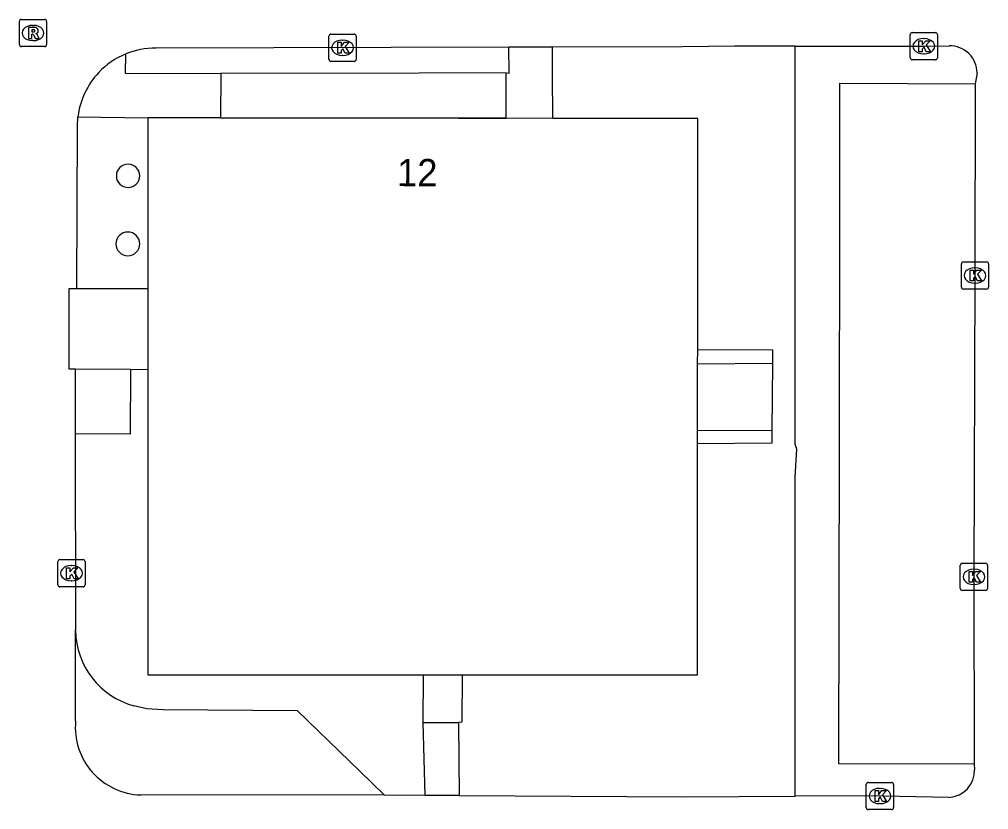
# Model space of a CAD drawing. Extents: x 161477 to 163040, y 383680 to 384868.
# Drawn here: x 161893.36 to 161928.97, y 384085.24 to 384114.29 of the extents above; entities that cross this region are included whole.
import ezdxf

# ---------------------------------------------------------------- set-up
doc = ezdxf.new("R2010")
doc.units = 0
for name, color, linetype in [('IMGEO_Dek', 7, 'Continuous'), ('IMGEO_Kolk', 7, 'Continuous'), ('IMGEO_Opslagtank', 7, 'Continuous'), ('IMGEO_Pand', 7, 'Continuous'), ('IMGEO_Pand_nummerreeks', 7, 'Continuous'), ('IMGEO_Parkeervlak_open', 7, 'Continuous'), ('IMGEO_Rijbaan_lokaal_open', 7, 'Continuous'), ('IMGEO_Rioolput', 7, 'Continuous'), ('IMGEO_Voetpad_halfverhard', 7, 'Continuous'), ('IMGEO_Voetpad_open', 7, 'Continuous')]:
    doc.layers.add(name, color=color, linetype=linetype)

msp = doc.modelspace()

# ---------------------------------------------------------------- linework, layer by layer
at = {"layer": 'IMGEO_Dek'}
msp.add_lwpolyline([(161911.242, 384112.317), (161908.043, 384112.311), (161900.763, 384112.296), (161900.748, 384110.668), (161909.493, 384110.653), (161911.237, 384110.65)], close=True, dxfattribs=at)
at = {"layer": 'IMGEO_Kolk'}
for p, q in [((161904.731, 384112.818), (161904.731, 384113.67)), ((161904.806, 384113.744), (161905.658, 384113.744)), ((161905.732, 384113.67), (161905.732, 384112.818)), ((161926.086, 384112.873), (161926.086, 384113.725)), ((161926.161, 384113.799), (161927.013, 384113.799)), ((161927.087, 384113.725), (161927.087, 384112.873)), ((161905.219, 384113.524), (161905.244, 384113.524)), ((161926.574, 384113.579), (161926.599, 384113.579)), ((161905.242, 384112.964), (161905.217, 384112.964)), ((161926.597, 384113.019), (161926.572, 384113.019)), ((161905.658, 384112.744), (161904.806, 384112.744)), ((161927.013, 384112.799), (161926.161, 384112.799)), ((161927.966, 384104.446), (161927.966, 384105.298)), ((161928.041, 384105.372), (161928.893, 384105.372)), ((161928.454, 384105.152), (161928.479, 384105.152)), ((161928.967, 384105.298), (161928.967, 384104.446)), ((161928.477, 384104.592), (161928.452, 384104.592)), ((161928.893, 384104.372), (161928.041, 384104.372)), ((161894.773, 384093.502), (161894.773, 384094.354)), ((161894.848, 384094.428), (161895.7, 384094.428)), ((161895.261, 384094.208), (161895.286, 384094.208)), ((161895.774, 384094.354), (161895.774, 384093.502)), ((161927.928, 384093.37), (161927.928, 384094.222)), ((161928.003, 384094.296), (161928.855, 384094.296)), ((161928.929, 384094.222), (161928.929, 384093.37)), ((161928.416, 384094.076), (161928.441, 384094.076)), ((161895.7, 384093.428), (161894.848, 384093.428)), ((161895.284, 384093.648), (161895.259, 384093.648)), ((161928.439, 384093.516), (161928.414, 384093.516)), ((161928.855, 384093.296), (161928.003, 384093.296)), ((161924.474, 384085.313), (161924.474, 384086.165)), ((161924.549, 384086.239), (161925.401, 384086.239)), ((161924.962, 384086.019), (161924.987, 384086.019)), ((161925.475, 384086.165), (161925.475, 384085.313)), ((161925.401, 384085.239), (161924.549, 384085.239)), ((161924.985, 384085.459), (161924.96, 384085.459))]:
    msp.add_line(p, q, dxfattribs=at)
for points in [[(161904.731, 384112.818), (161904.731, 384113.67)], [(161904.806, 384113.744), (161905.658, 384113.744)], [(161905.732, 384113.67), (161905.732, 384112.818)], [(161926.086, 384112.873), (161926.086, 384113.725)], [(161926.161, 384113.799), (161927.013, 384113.799)], [(161927.087, 384113.725), (161927.087, 384112.873)], [(161905.052, 384113.444), (161905.175, 384113.444), (161905.175, 384113.293), (161905.305, 384113.444), (161905.469, 384113.444), (161905.323, 384113.293), (161905.476, 384113.044), (161905.324, 384113.044), (161905.239, 384113.208), (161905.175, 384113.141), (161905.175, 384113.044), (161905.052, 384113.044), (161905.052, 384113.444)], [(161926.407, 384113.499), (161926.53, 384113.499), (161926.53, 384113.348), (161926.66, 384113.499), (161926.824, 384113.499), (161926.678, 384113.348), (161926.831, 384113.099), (161926.679, 384113.099), (161926.594, 384113.263), (161926.53, 384113.196), (161926.53, 384113.099), (161926.407, 384113.099), (161926.407, 384113.499)], [(161905.658, 384112.744), (161904.806, 384112.744)], [(161927.013, 384112.799), (161926.161, 384112.799)], [(161927.966, 384104.446), (161927.966, 384105.298)], [(161928.041, 384105.372), (161928.893, 384105.372)], [(161928.967, 384105.298), (161928.967, 384104.446)], [(161928.287, 384105.072), (161928.41, 384105.072), (161928.41, 384104.921), (161928.54, 384105.072), (161928.704, 384105.072), (161928.558, 384104.921), (161928.711, 384104.672), (161928.559, 384104.672), (161928.474, 384104.836), (161928.41, 384104.769), (161928.41, 384104.672), (161928.287, 384104.672), (161928.287, 384105.072)], [(161928.893, 384104.372), (161928.041, 384104.372)], [(161894.773, 384093.502), (161894.773, 384094.354)], [(161894.848, 384094.428), (161895.7, 384094.428)], [(161895.094, 384094.128), (161895.217, 384094.128), (161895.217, 384093.977), (161895.347, 384094.128), (161895.511, 384094.128), (161895.365, 384093.977), (161895.518, 384093.728), (161895.366, 384093.728), (161895.281, 384093.892), (161895.217, 384093.825), (161895.217, 384093.728), (161895.094, 384093.728), (161895.094, 384094.128)], [(161895.774, 384094.354), (161895.774, 384093.502)], [(161927.928, 384093.37), (161927.928, 384094.222)], [(161928.003, 384094.296), (161928.855, 384094.296)], [(161928.929, 384094.222), (161928.929, 384093.37)], [(161928.249, 384093.996), (161928.372, 384093.996), (161928.372, 384093.845), (161928.502, 384093.996), (161928.666, 384093.996), (161928.52, 384093.845), (161928.673, 384093.596), (161928.521, 384093.596), (161928.436, 384093.76), (161928.372, 384093.693), (161928.372, 384093.596), (161928.249, 384093.596), (161928.249, 384093.996)], [(161895.7, 384093.428), (161894.848, 384093.428)], [(161928.855, 384093.296), (161928.003, 384093.296)], [(161924.474, 384085.313), (161924.474, 384086.165)], [(161924.549, 384086.239), (161925.401, 384086.239)], [(161924.795, 384085.939), (161924.918, 384085.939), (161924.918, 384085.788), (161925.048, 384085.939), (161925.212, 384085.939), (161925.066, 384085.788), (161925.219, 384085.539), (161925.067, 384085.539), (161924.982, 384085.703), (161924.918, 384085.636), (161924.918, 384085.539), (161924.795, 384085.539), (161924.795, 384085.939)], [(161925.475, 384086.165), (161925.475, 384085.313)], [(161925.401, 384085.239), (161924.549, 384085.239)]]:
    msp.add_lwpolyline(points, dxfattribs=at)
for centre, start, end in [((161904.808, 384113.668), 91.552, 178.448), ((161904.808, 384113.668), 91.552, 178.448), ((161905.656, 384113.668), 1.552, 88.448), ((161905.656, 384113.668), 1.552, 88.448), ((161926.163, 384113.723), 91.552, 178.448), ((161926.163, 384113.723), 91.552, 178.448), ((161927.011, 384113.723), 1.552, 88.448), ((161927.011, 384113.723), 1.552, 88.448), ((161904.808, 384112.82), 181.552, 268.448), ((161904.808, 384112.82), 181.552, 268.448), ((161905.656, 384112.82), 271.552, 358.448), ((161905.656, 384112.82), 271.552, 358.448), ((161926.163, 384112.875), 181.552, 268.448), ((161926.163, 384112.875), 181.552, 268.448), ((161927.011, 384112.875), 271.552, 358.448), ((161927.011, 384112.875), 271.552, 358.448), ((161928.043, 384105.296), 91.552, 178.448), ((161928.043, 384105.296), 91.552, 178.448), ((161928.891, 384105.296), 1.552, 88.448), ((161928.891, 384105.296), 1.552, 88.448), ((161928.043, 384104.448), 181.552, 268.448), ((161928.043, 384104.448), 181.552, 268.448), ((161928.891, 384104.448), 271.552, 358.448), ((161928.891, 384104.448), 271.552, 358.448), ((161894.85, 384094.352), 91.552, 178.448), ((161894.85, 384094.352), 91.552, 178.448), ((161895.698, 384094.352), 1.552, 88.448), ((161895.698, 384094.352), 1.552, 88.448), ((161928.005, 384094.22), 91.552, 178.448), ((161928.005, 384094.22), 91.552, 178.448), ((161928.853, 384094.22), 1.552, 88.448), ((161928.853, 384094.22), 1.552, 88.448), ((161894.85, 384093.504), 181.552, 268.448), ((161894.85, 384093.504), 181.552, 268.448), ((161895.698, 384093.504), 271.552, 358.448), ((161895.698, 384093.504), 271.552, 358.448), ((161928.005, 384093.372), 181.552, 268.448), ((161928.005, 384093.372), 181.552, 268.448), ((161928.853, 384093.372), 271.552, 358.448), ((161928.853, 384093.372), 271.552, 358.448), ((161924.551, 384086.163), 91.552, 178.448), ((161924.551, 384086.163), 91.552, 178.448), ((161925.399, 384086.163), 1.552, 88.448), ((161925.399, 384086.163), 1.552, 88.448), ((161924.551, 384085.315), 181.552, 268.448), ((161924.551, 384085.315), 181.552, 268.448), ((161925.399, 384085.315), 271.552, 358.448), ((161925.399, 384085.315), 271.552, 358.448)]:
    msp.add_arc(centre, 0.0765, start, end, dxfattribs=at)
for centre, major_axis, ratio, start_param, end_param in [((161905.218, 384113.244), (-0.387, 0.002), 0.722429, 4.712389, 7.853982), ((161905.243, 384113.244), (-0.39, 0.002), 0.717154, 1.570796, 4.712389), ((161926.573, 384113.299), (-0.387, 0.002), 0.722429, 4.712389, 7.853982), ((161926.598, 384113.299), (-0.39, 0.002), 0.717154, 1.570796, 4.712389), ((161928.453, 384104.872), (-0.387, 0.002), 0.722429, 4.712389, 7.853982), ((161928.478, 384104.872), (-0.39, 0.002), 0.717154, 1.570796, 4.712389), ((161895.26, 384093.928), (-0.387, 0.002), 0.722429, 4.712389, 7.853982), ((161895.285, 384093.928), (-0.39, 0.002), 0.717154, 1.570796, 4.712389), ((161928.415, 384093.796), (-0.387, 0.002), 0.722429, 4.712389, 7.853982), ((161928.44, 384093.796), (-0.39, 0.002), 0.717154, 1.570796, 4.712389), ((161924.961, 384085.739), (-0.387, 0.002), 0.722429, 4.712389, 7.853982), ((161924.986, 384085.739), (-0.39, 0.002), 0.717154, 1.570796, 4.712389)]:
    msp.add_ellipse(centre, major_axis=major_axis, ratio=ratio, start_param=start_param, end_param=end_param, dxfattribs=at)
at = {"layer": 'IMGEO_Opslagtank'}
for centre, radius, start, end in [((161897.351, 384108.535), 0.428, 359.933, 269.933), ((161897.35, 384108.536), 0.428, 270.0648, 359.8012), ((161897.342, 384106.033), 0.437, 90.0656, 359.9344), ((161897.341, 384106.032), 0.437, 0.0025, 89.9975)]:
    msp.add_arc(centre, radius, start, end, dxfattribs=at)
at = {"layer": 'IMGEO_Pand'}
for points in [[(161898.081, 384110.673), (161898.08, 384104.395)], [(161900.748, 384110.668), (161898.081, 384110.673)], [(161911.237, 384110.65), (161909.493, 384110.653), (161900.748, 384110.668)], [(161912.952, 384110.647), (161911.237, 384110.65)], [(161918.279, 384102.154), (161918.288, 384110.637), (161912.952, 384110.647)], [(161898.08, 384104.395), (161898.079, 384101.41)], [(161918.278, 384101.63), (161918.279, 384102.154)], [(161918.276, 384099.17), (161918.278, 384101.63)], [(161898.079, 384101.41), (161898.078, 384096.699), (161898.078, 384094.245), (161898.077, 384090.199), (161908.204, 384090.196)], [(161918.275, 384098.69), (161918.276, 384099.17)], [(161909.624, 384090.196), (161918.266, 384090.194), (161918.275, 384098.69)], [(161908.204, 384090.196), (161909.624, 384090.196)]]:
    msp.add_lwpolyline(points, dxfattribs=at)
at = {"layer": 'IMGEO_Parkeervlak_open'}
msp.add_lwpolyline([(161928.44, 384086.908), (161923.462, 384086.921), (161923.483, 384098.676), (161923.503, 384107.023), (161923.498, 384111.939), (161928.47, 384111.914)], dxfattribs=at)
at = {"layer": 'IMGEO_Rijbaan_lokaal_open'}
for points in [[(161911.338, 384113.266), (161898.379, 384113.23)], [(161912.946, 384113.27), (161911.338, 384113.266)], [(161921.866, 384113.297), (161919.637, 384113.296), (161917.724, 384113.283), (161912.946, 384113.27)], [(161921.866, 384113.297), (161926.587, 384113.3), (161927.523, 384113.312)], [(161928.542, 384112.318), (161928.47, 384111.914)], [(161928.47, 384111.914), (161928.467, 384104.873), (161928.429, 384093.797), (161928.44, 384086.908)], [(161895.469, 384104.397), (161895.491, 384110.351), (161895.511, 384110.71)], [(161895.422, 384101.427), (161895.192, 384101.427), (161895.189, 384104.397), (161895.469, 384104.397)], [(161895.424, 384099.051), (161895.422, 384101.427)], [(161895.426, 384091.816), (161895.427, 384091.877), (161895.429, 384094.247), (161895.426, 384096.705), (161895.424, 384099.051)], [(161895.423, 384088.499), (161895.426, 384091.816)], [(161928.44, 384086.908), (161928.451, 384086.709)], [(161906.777, 384085.765), (161897.819, 384085.777)], [(161908.266, 384085.762), (161906.777, 384085.765)], [(161909.516, 384085.763), (161908.266, 384085.762)], [(161909.516, 384085.763), (161917.738, 384085.714), (161921.866, 384085.737)], [(161927.512, 384085.687), (161924.475, 384085.751), (161921.866, 384085.737)]]:
    msp.add_lwpolyline(points, dxfattribs=at)
for centre, radius, start, end in [((161898.349, 384110.382), 2.849, 112.6072, 136.7222), ((161898.35, 384110.369), 2.861, 89.4148, 112.5186), ((161927.55, 384112.32), 0.992, 359.8798, 91.5432), ((161898.348, 384110.368), 2.857, 136.506, 173.1325), ((161897.905, 384088.268), 2.493, 174.6836, 268.0271), ((161927.46, 384086.677), 0.991, 272.9889, 1.8583)]:
    msp.add_arc(centre, radius, start, end, dxfattribs=at)
at = {"layer": 'IMGEO_Rioolput'}
for p, q in [((161893.358, 384113.36), (161893.358, 384114.212)), ((161893.433, 384114.286), (161894.285, 384114.286)), ((161893.846, 384114.066), (161893.871, 384114.066)), ((161894.359, 384114.212), (161894.359, 384113.36)), ((161893.869, 384113.506), (161893.844, 384113.506)), ((161894.285, 384113.286), (161893.433, 384113.286))]:
    msp.add_line(p, q, dxfattribs=at)
for points in [[(161893.358, 384113.36), (161893.358, 384114.212)], [(161893.433, 384114.286), (161894.285, 384114.286)], [(161894.359, 384114.212), (161894.359, 384113.36)], [(161893.947, 384113.984), (161893.695, 384113.986), (161893.695, 384113.586)], [(161893.695, 384113.586), (161893.819, 384113.586), (161893.819, 384113.748), (161893.83, 384113.748)], [(161893.873, 384113.905), (161893.819, 384113.905), (161893.819, 384113.824)], [(161893.819, 384113.824), (161893.871, 384113.824)], [(161893.877, 384113.719), (161893.948, 384113.586), (161894.088, 384113.586), (161894.023, 384113.712)], [(161894.285, 384113.286), (161893.433, 384113.286)]]:
    msp.add_lwpolyline(points, dxfattribs=at)
for centre, radius, start, end in [((161893.435, 384114.21), 0.0765, 91.552, 178.448), ((161893.435, 384114.21), 0.0765, 91.552, 178.448), ((161894.283, 384114.21), 0.0765, 1.552, 88.448), ((161894.283, 384114.21), 0.0765, 1.552, 88.448), ((161893.829, 384113.695), 0.0533, 26.0293, 88.6989), ((161893.855, 384114.013), 0.19, 274.7715, 282.9687), ((161893.879, 384113.809), 0.0964, 77.0061, 93.1865), ((161893.893, 384113.866), 0.0378, 276.6634, 79.6772), ((161893.946, 384113.874), 0.109, 350.3612, 89.416), ((161893.944, 384113.874), 0.112, 277.5842, 350.9817), ((161893.928, 384113.659), 0.108, 29.5134, 73.7905), ((161893.435, 384113.362), 0.0765, 181.552, 268.448), ((161893.435, 384113.362), 0.0765, 181.552, 268.448), ((161894.283, 384113.362), 0.0765, 271.552, 358.448), ((161894.283, 384113.362), 0.0765, 271.552, 358.448)]:
    msp.add_arc(centre, radius, start, end, dxfattribs=at)
for centre, major_axis, ratio, start_param, end_param in [((161893.845, 384113.786), (-0.387, 0.002), 0.722429, 4.712389, 7.853982), ((161893.87, 384113.786), (-0.39, 0.002), 0.717154, 1.570796, 4.712389)]:
    msp.add_ellipse(centre, major_axis=major_axis, ratio=ratio, start_param=start_param, end_param=end_param, dxfattribs=at)
at = {"layer": 'IMGEO_Voetpad_halfverhard'}
for points in [[(161921.866, 384085.737), (161921.866, 384097.461), (161921.918, 384098.494), (161921.866, 384098.677), (161921.866, 384099.154), (161921.866, 384101.655), (161921.866, 384113.297)], [(161918.279, 384102.154), (161921.026, 384102.142), (161921.023, 384101.649)], [(161921.009, 384099.158), (161921.006, 384098.71), (161918.275, 384098.69)], [(161908.195, 384088.44), (161908.204, 384090.196)], [(161909.624, 384090.196), (161909.615, 384088.454), (161909.494, 384088.441)], [(161897.559, 384089.06), (161898.042, 384088.951), (161898.637, 384088.917), (161903.562, 384088.881), (161905.88, 384086.635), (161906.777, 384085.765)]]:
    msp.add_lwpolyline(points, dxfattribs=at)
msp.add_arc((161898.31, 384091.844), 2.884, 180.5619, 254.9141, dxfattribs=at)
at = {"layer": 'IMGEO_Voetpad_open'}
for points in [[(161897.254, 384113.012), (161897.243, 384112.304), (161900.763, 384112.296), (161900.748, 384110.668)], [(161911.237, 384110.65), (161911.242, 384112.317), (161911.352, 384112.315), (161911.338, 384113.266)], [(161912.952, 384110.647), (161912.948, 384112.29), (161912.946, 384113.27)], [(161911.242, 384112.317), (161908.043, 384112.311), (161900.763, 384112.296), (161900.748, 384110.668), (161909.493, 384110.653), (161911.237, 384110.65), (161911.242, 384112.317)], [(161895.511, 384110.71), (161898.081, 384110.673)], [(161895.469, 384104.397), (161898.08, 384104.395)], [(161918.278, 384101.63), (161921.023, 384101.649)], [(161921.023, 384101.649), (161921.009, 384099.158)], [(161897.439, 384101.411), (161895.422, 384101.427)], [(161897.439, 384101.411), (161897.434, 384099.035), (161895.424, 384099.051)], [(161898.079, 384101.41), (161897.439, 384101.411)], [(161921.009, 384099.158), (161918.276, 384099.17)], [(161908.195, 384088.44), (161909.494, 384088.441)], [(161908.266, 384085.762), (161908.195, 384088.44)], [(161909.494, 384088.441), (161909.516, 384085.763)]]:
    msp.add_lwpolyline(points, dxfattribs=at)

# ---------------------------------------------------------------- texts
at = {"layer": 'IMGEO_Pand_nummerreeks'}
msp.add_text('12', height=1, rotation=359.9026, dxfattribs=at).set_placement((161907.232, 384108.156))

doc.saveas('drawing.dxf')
